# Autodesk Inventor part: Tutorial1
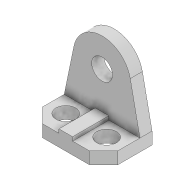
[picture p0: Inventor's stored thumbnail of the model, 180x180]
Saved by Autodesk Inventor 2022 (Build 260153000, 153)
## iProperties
Created: 2021-03
Part Number: Tutorial1
Material: Generic
Document SubType Name: Modeling
Designer: ASUS Laptop
Density: 1 g/cm^3
Appearance: Default
Author: ASUS Laptop
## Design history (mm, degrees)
sketch "Sketch1"
  geometry: L1 (0, 0)-(-200, 0); L2 (-200, 0)-(-200, 90); L3 (-200, 90)-(-162, 128); L4 (-162, 128)-(-38, 128); L5 (-38, 128)-(0, 90); L6 (0, 90)-(0, 0); L7 (-154, 74)-(-31.817, 74); C1 r 26 at (-154, 74); C2 r 26 at (-46, 74); 1 further point
  constraints: 14 end point, 2 centre point, 2 horizontal, 2 parallel, 2 perpendicular, 1 coincident, 1 equal radius, 1 point on line
  dimensions: "d0" = 128 distance between parallel lines of L4 L1; "d1" = 90 distance of L1.end L2.end; "d2" = 124 distance of L3.end L4.end; "d3" = 38 horizontal distance of L3.end L2.end; "d4" = 38 horizontal distance of L5.end L4.end; "d5" = 46 distance from line of L7.start L2; "d6" = 46 distance from line of L6 C2.centre; "d7" = 74 distance from line of L7.start L1; "d8" = 52 diameter of C2
extrude "Extrusion1" new body sketch "Sketch1" distance "d9" = 32; taper "d10" = 0 deg
sketch "Sketch2"
  geometry: L1 (200, 32)-(162, 32) reference; L2 (200, 32)-(174.418, 155.424); L3 (38, 32)-(0, 32) reference; L4 (25.582, 155.424)-(0, 32); L5 (0, 32)-(200, 32); L6 (162, 0)-(38, 0) reference; L7 (100, 0)-(100, 176.194); C1 r 27.5 at (100, 140); A1 r 76 centre (100, 140) between (174.418, 155.424) and (25.582, 155.424); 3 further points
  constraints: 8 end point, 2 centre point, 2 point on circle, 2 tangent, 1 coincident, 1 collinear, 1 midpoint, 1 vertical, 1 other
  dimensions: "d11" = 76 radius of A1; "d12" = 108 distance from line of A1.centre L5; "d13" = 55 diameter of C1
extrude "Extrusion2" join sketch "Sketch2" distance "d14" = 32; taper "d15" = 0 deg
sketch "Sketch3"
  geometry: 1 further point
sketch "Sketch4"
  geometry: L1 (0, 32)-(124, 32) reference; L2 (44, 32)-(80, 32); L3 (80, 32)-(80, 42); L4 (80, 42)-(44, 42); L5 (44, 42)-(44, 32); L6 (-38, 0)-(-38, 32) reference; 1 further point
  constraints: 8 end point, 2 parallel, 1 horizontal, 1 perpendicular, 1 point on line
  dimensions: "d16" = 36 distance of L3.end L4.end; "d17" = 10 distance of L4.end L2.start; "d18" = 82 distance between parallel lines of L5 L6
extrude "Extrusion3" join sketch "Sketch4" stored distance "d19" = 32; taper "d20" = 0 deg
body "Solid1"
